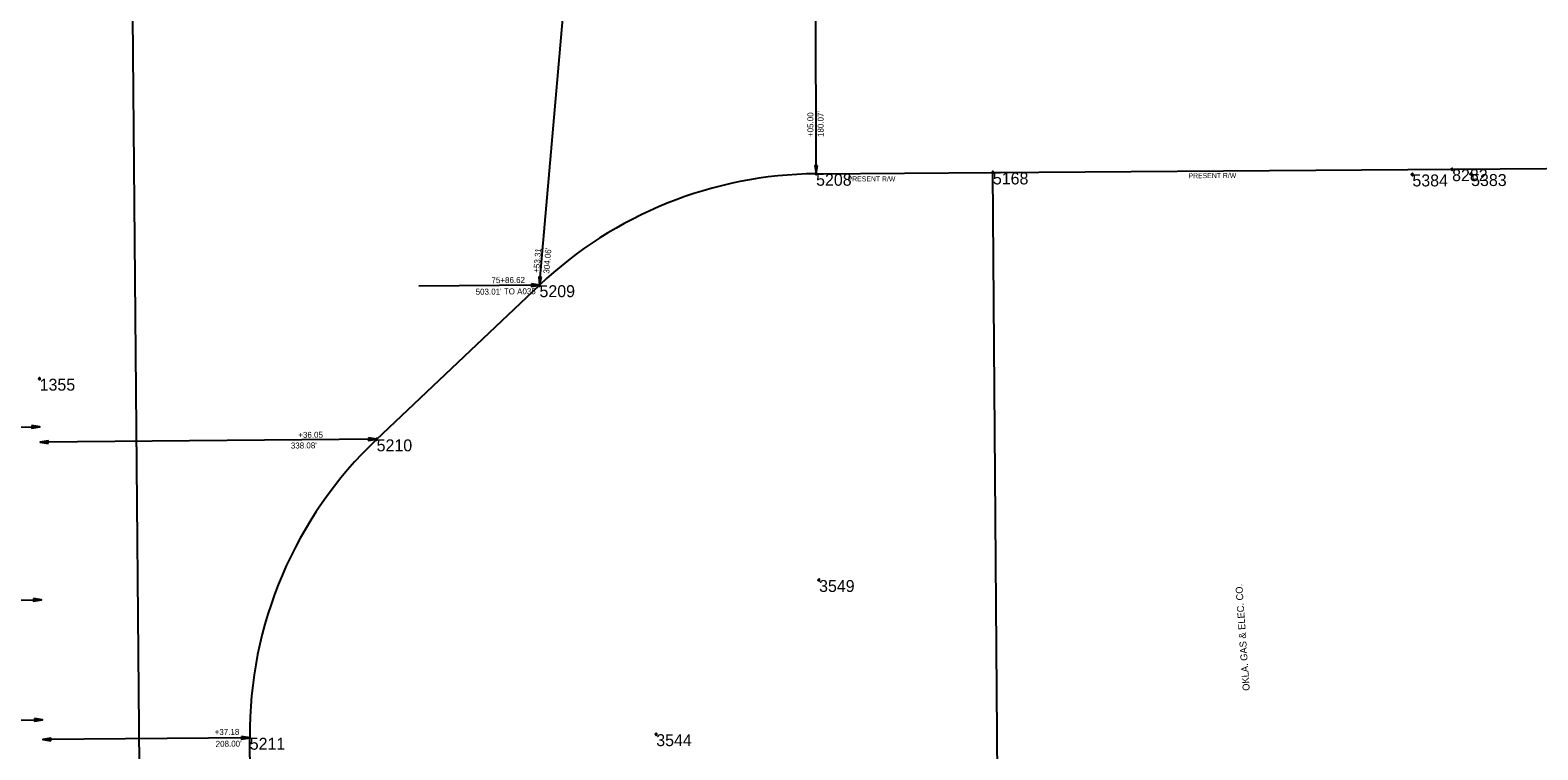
# Model space of a CAD drawing. Extents: x 2145146 to 2158053, y 137507 to 150829.
# Drawn here: x 2150819 to 2152334, y 142146 to 142870 of the extents above; entities that cross this region are included whole.
import ezdxf

# ---------------------------------------------------------------- set-up
doc = ezdxf.new("R2010")
doc.units = 0
for name, color, linetype in [('ALIGN_Cogo Points', 7, 'Continuous'), ('ALIGN_ROW Dimension', 7, 'Continuous'), ('ALIGN_ROW Line', 7, 'Continuous'), ('ALIGN_ROW Text', 7, 'Continuous'), ('PLSS_Property Line', 7, 'Continuous'), ('PLSS_Section Line', 7, 'Continuous'), ('PLSS_Text_TURNED OFF', 7, 'Continuous')]:
    doc.layers.add(name, color=color, linetype=linetype)

# ---------------------------------------------------------------- blocks, each defined once
blk = doc.blocks.new('Arrowhd')
at = {"layer": 'PLSS_Property Line'}
blk.add_lwpolyline([(0.125, -0.021), (0.125, 0.021), (0, 0)], close=True, dxfattribs=at)

msp = doc.modelspace()

# ---------------------------------------------------------------- linework, layer by layer
at = {"layer": 'ALIGN_Cogo Points'}
for points in [[(2151609, 142725.2), (2151609, 142726.4), (2151609, 142725.2), (2151607.8, 142725.2), (2151609, 142725.2), (2151609, 142724), (2151609, 142725.2), (2151610.2, 142725.2)], [(2151786.6, 142726.5), (2151786.6, 142727.7), (2151786.6, 142726.5), (2151785.4, 142726.5), (2151786.6, 142726.5), (2151786.6, 142725.3), (2151786.6, 142726.5), (2151787.8, 142726.5)], [(2152208.1, 142724.5), (2152208.1, 142725.7), (2152208.1, 142724.5), (2152206.9, 142724.5), (2152208.1, 142724.5), (2152208.1, 142723.3), (2152208.1, 142724.5), (2152209.3, 142724.5)], [(2152248, 142729.8), (2152248, 142731), (2152248, 142729.8), (2152246.8, 142729.8), (2152248, 142729.8), (2152248, 142728.6), (2152248, 142729.8), (2152249.2, 142729.8)], [(2152267.1, 142724.9), (2152267.1, 142726.1), (2152267.1, 142724.9), (2152265.9, 142724.9), (2152267.1, 142724.9), (2152267.1, 142723.7), (2152267.1, 142724.9), (2152268.3, 142724.9)], [(2151331.1, 142613.2), (2151331.1, 142614.4), (2151331.1, 142613.2), (2151329.9, 142613.2), (2151331.1, 142613.2), (2151331.1, 142612), (2151331.1, 142613.2), (2151332.3, 142613.2)], [(2150828.9, 142519.2), (2150828.9, 142520.4), (2150828.9, 142519.2), (2150827.7, 142519.2), (2150828.9, 142519.2), (2150828.9, 142518), (2150828.9, 142519.2), (2150830.1, 142519.2)], [(2151167.5, 142458.2), (2151167.5, 142459.4), (2151167.5, 142458.2), (2151166.3, 142458.2), (2151167.5, 142458.2), (2151167.5, 142457), (2151167.5, 142458.2), (2151168.7, 142458.2)], [(2151612, 142316.8), (2151612, 142318), (2151612, 142316.8), (2151610.8, 142316.8), (2151612, 142316.8), (2151612, 142315.6), (2151612, 142316.8), (2151613.2, 142316.8)], [(2151040, 142158.2), (2151040, 142159.4), (2151040, 142158.2), (2151038.8, 142158.2), (2151040, 142158.2), (2151040, 142157), (2151040, 142158.2), (2151041.2, 142158.2)], [(2151448.4, 142161.8), (2151448.4, 142163), (2151448.4, 142161.8), (2151447.2, 142161.8), (2151448.4, 142161.8), (2151448.4, 142160.6), (2151448.4, 142161.8), (2151449.6, 142161.8)]]:
    msp.add_lwpolyline(points, dxfattribs=at)
at = {"layer": 'ALIGN_ROW Dimension'}
for points in [[(2151331.1, 142613.2), (2151357.6, 142916.2)], [(2151609, 142725.2), (2151608.9, 142905.3)], [(2151331.1, 142613.2), (2151210, 142612.2)], [(2150529.1, 142468.1), (2150829.3, 142470.8)], [(2151167.5, 142458.3), (2150829.4, 142455.3)], [(2150631.5, 142295), (2150830.8, 142296.8)], [(2150668.1, 142174.8), (2150831.9, 142176.3)], [(2151040, 142158.2), (2150832, 142156.4)], [(2151040, 142158.2), (2150832, 142156.4)]]:
    msp.add_lwpolyline(points, dxfattribs=at)
at = {"layer": 'ALIGN_ROW Line'}
for points in [[(2151609, 142725.2), (2151786.6, 142726.5), (2152528.1, 142731.8), (2152528.1, 142731.8)], [(2151167.5, 142458.2), (2151167.5, 142458.2), (2151331.1, 142613.2)], [(2151043.4, 141772.1), (2151040, 142158.2)]]:
    msp.add_lwpolyline(points, dxfattribs=at)
for centre, start, end in [((2151612, 142316.8), 90.4098, 133.4598), ((2151448.4, 142161.8), 133.4598, 180.5015)]:
    msp.add_arc(centre, 408.4, start, end, dxfattribs=at)
at = {"layer": 'PLSS_Property Line'}
msp.add_lwpolyline([(2151049.8, 141678.8), (2151794.6, 141684.3), (2151786.6, 142726.5)], dxfattribs=at)
at = {"layer": 'PLSS_Section Line'}
msp.add_lwpolyline([(2150945, 140358.9), (2150921.7, 142997.3)], dxfattribs=at)

# ---------------------------------------------------------------- block references
at = {"layer": 'ALIGN_ROW Dimension'}
for p, xscale, yscale, rotation in [((2151609, 142725.2), 65.00000000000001, 65, 90.03436369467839), ((2151331.1, 142613.2), 65.00000000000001, 64.99999999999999, -179.49850748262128), ((2151331.1, 142613.2), 65, 65, 85.0006822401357), ((2150829.2, 142470.8), 65, 65, 180), ((2150829.4, 142455.3), 65.00000000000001, 65, 0.7805293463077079), ((2151167.4, 142458.3), 65, 65, 180), ((2150830.8, 142296.8), 65, 65, 180), ((2150831.8, 142176.3), 65, 65, 180), ((2151040, 142158.2), 65, 65, 180), ((2150832, 142156.4), 65.00000000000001, 65, 0.7805293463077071)]:
    msp.add_blockref('Arrowhd', p, dxfattribs=dict(at, xscale=xscale, yscale=yscale, rotation=rotation))

# ---------------------------------------------------------------- texts
at = {"layer": 'ALIGN_Cogo Points'}
for s, p in [('5208', (2151609, 142713.2)), ('5168', (2151786.6, 142714.5)), ('5384', (2152208.1, 142712.5)), ('8282', (2152248, 142717.8)), ('5383', (2152267.1, 142712.9)), ('5209', (2151331.1, 142601.2)), ('1355', (2150828.9, 142507.2)), ('5210', (2151167.5, 142446.2)), ('3549', (2151612, 142304.8)), ('3544', (2151448.4, 142149.8)), ('5211', (2151040, 142146.2))]:
    msp.add_text(s, height=12, dxfattribs=at).set_placement(p)
at = {"layer": 'ALIGN_ROW Dimension'}
for s, rotation, p in [('+05.00', 90, (2151606.3, 142762.2)), ("180.07'", 90, (2151616.5, 142762.2)), ('+53.31', 85.0738, (2151330.8, 142625.5)), ("304.06'", 85.0738, (2151340.9, 142624.6)), ('75+86.62', 0.5632, (2151282.9, 142615.2)), ("503.01' TO A035", 0.5632, (2151267, 142603.6)), ('+36.05', 0.3718, (2151088.8, 142459.7)), ("338.08'", 0.3718, (2151081.3, 142449)), ('+37.18', 0.3718, (2151004.8, 142161)), ("208.00'", 0.3718, (2151005.8, 142149.1))]:
    msp.add_text(s, height=6, rotation=rotation, dxfattribs=at).set_placement(p)
at = {"layer": 'ALIGN_ROW Text'}
for rotation, p in [(359.9447, (2151640.7, 142717.6)), (0.4729, (2151983.2, 142720.7))]:
    msp.add_text('PRESENT R/W', height=5, rotation=rotation, dxfattribs=at).set_placement(p)
at = {"layer": 'PLSS_Text_TURNED OFF'}
msp.add_text('OKLA. GAS & ELEC. CO.', height=7, rotation=94.0054, dxfattribs=at).set_placement((2152044.7, 142205.7))

doc.saveas('drawing.dxf')
